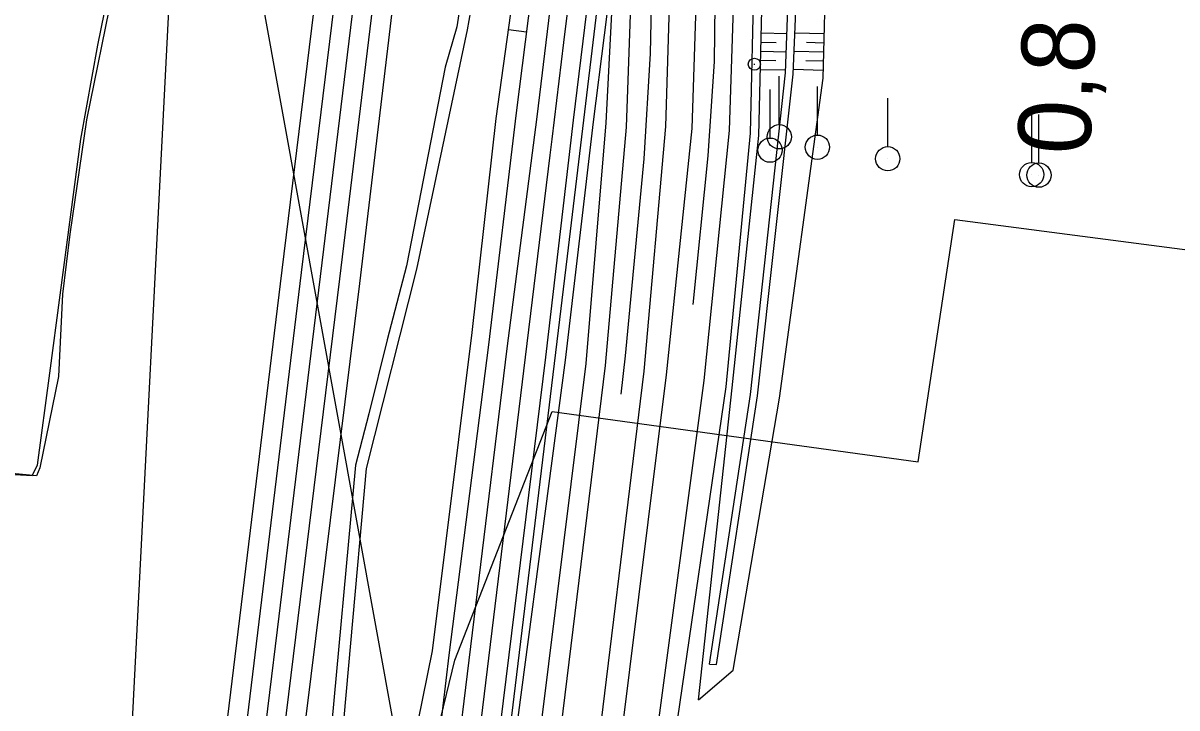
# Model space of a CAD drawing. Extents: x -598638 to -597933, y -1164002 to -1161904.
# Drawn here: x -598553.5 to -598458.3, y -1163554 to -1163497.5 of the extents above; entities that cross this region are included whole.
import ezdxf

# ---------------------------------------------------------------- set-up
doc = ezdxf.new("R2010")
doc.units = 0
for name, color, linetype in [('Vrstva 1', 7, 'Continuous'), ('Vrstva 13', 7, 'Continuous'), ('Vrstva 26', 7, 'Continuous'), ('Vrstva 28', 7, 'Continuous'), ('Vrstva 31', 7, 'Continuous'), ('Vrstva 32', 7, 'Continuous'), ('Vrstva 37', 7, 'Continuous'), ('Vrstva 4', 7, 'Continuous'), ('Vrstva 44', 7, 'Continuous'), ('Vrstva 48', 7, 'Continuous'), ('Vrstva 49', 7, 'Continuous'), ('Vrstva 51', 7, 'Continuous'), ('Vrstva 63', 7, 'Continuous'), ('Vrstva 7', 7, 'Continuous')]:
    doc.layers.add(name, color=color, linetype=linetype)

msp = doc.modelspace()

# ---------------------------------------------------------------- linework, layer by layer
at = {"layer": 'Vrstva 1'}
for points in [[(-598540.061, -1163609.51), (-598538.55, -1163597.18), (-598535.661, -1163573.393), (-598532.502, -1163547.551), (-598529.47, -1163522.734), (-598526.451, -1163497.915), (-598523.419, -1163473.102), (-598521.347, -1163456.074), (-598520.4, -1163448.28), (-598517.374, -1163423.469), (-598514.348, -1163398.653), (-598511.323, -1163373.834), (-598509.75, -1163360.838), (-598508.294, -1163349.021), (-598507.057, -1163338.802)], [(-598533.109, -1163697.673), (-598530.082, -1163672.857), (-598527.054, -1163648.041), (-598524.024, -1163623.225), (-598522.508, -1163610.684), (-598520.997, -1163598.409), (-598517.97, -1163573.59), (-598514.943, -1163548.774), (-598511.916, -1163523.964), (-598510.022, -1163508.437), (-598509.85, -1163507.121), (-598508.889, -1163499.148), (-598506.121, -1163476.682), (-598505.865, -1163474.332), (-598504.943, -1163466.8)], [(-598504.166, -1163528.146), (-598503.792, -1163524.977), (-598502.276, -1163508.73), (-598501.741, -1163500.062), (-598501.244, -1163476.517), (-598501.25, -1163475.071), (-598501.424, -1163467.022)], [(-598498.227, -1163520.757), (-598496.987, -1163508.5), (-598496.459, -1163500.705), (-598496.171, -1163474.917)]]:
    msp.add_lwpolyline(points, dxfattribs=at)
at = {"layer": 'Vrstva 13'}
for points in [[(-598496.865, -1163550.379), (-598493.505, -1163528.163), (-598490.621, -1163501.64), (-598489.924, -1163482.727), (-598490.976, -1163458.949), (-598491.652, -1163439.005), (-598492.756, -1163420.248), (-598491.376, -1163405.706)], [(-598496.865, -1163550.379), (-598496.294, -1163550.405), (-598492.926, -1163528.273), (-598489.969, -1163501.763), (-598489.191, -1163482.813), (-598490.216, -1163459.012), (-598491.02, -1163438.946), (-598492.756, -1163420.248)]]:
    msp.add_lwpolyline(points, dxfattribs=at)
at = {"layer": 'Vrstva 26'}
for points in [[(-598431.799, -1163480.405), (-598431.417, -1163476.751), (-598432.69, -1163475.729), (-598442.616, -1163474.624), (-598460.759, -1163472.82), (-598477.038, -1163471.243), (-598477.967, -1163471.597), (-598478.577, -1163472.787), (-598480.967, -1163481.186), (-598482.275, -1163484.404), (-598483.524, -1163485.456), (-598486.811, -1163485.386), (-598490.508, -1163485.536), (-598512.602, -1163485.892), (-598514.382, -1163486.347), (-598515.51, -1163489.284), (-598515.761, -1163490.906), (-598516.173, -1163494.221), (-598516.873, -1163498.106), (-598521.044, -1163517.837), (-598525.187, -1163534.255), (-598527.784, -1163563.046)], [(-598588.761, -1163677.265), (-598581.48, -1163677.548), (-598580.673, -1163676.998), (-598579.793, -1163670.74), (-598579.104, -1163665.83), (-598575.81, -1163633.898), (-598573.543, -1163615.779), (-598569.61, -1163583.767), (-598565.804, -1163555.196), (-598563.346, -1163534.245), (-598552.733, -1163534.833), (-598552.296, -1163533.988), (-598551.287, -1163526.393), (-598548.728, -1163507.111), (-598547.312, -1163499.378), (-598545.332, -1163489.631)]]:
    msp.add_lwpolyline(points, dxfattribs=at)
at = {"layer": 'Vrstva 28'}
for points in [[(-598454.474, -1163473.952), (-598465.142, -1163473.014), (-598476.47, -1163471.867), (-598477.633, -1163472.175), (-598478.209, -1163473.453), (-598480.422, -1163481.099), (-598481.698, -1163484.769), (-598483.15, -1163485.678), (-598488.83, -1163486.39), (-598490.871, -1163486.311), (-598512.372, -1163485.579), (-598514.383, -1163486.119), (-598515.446, -1163487.289), (-598516.135, -1163489.246), (-598516.85, -1163491.33), (-598516.981, -1163492.995), (-598517.712, -1163497.862), (-598518.68, -1163501.19), (-598521.851, -1163517.567), (-598523.45, -1163523.66), (-598524.97, -1163529.75), (-598526.071, -1163533.98), (-598528.23, -1163557.57)], [(-598545.092, -1163489.642), (-598546.067, -1163494.842), (-598548.252, -1163505.51), (-598549.637, -1163514.935), (-598550.222, -1163519.898), (-598550.57, -1163526.69), (-598552.088, -1163534.212), (-598552.387, -1163534.867), (-598558.986, -1163534.224), (-598563.192, -1163534.27), (-598563.517, -1163536.001), (-598564.063, -1163540.493), (-598564.734, -1163547.322), (-598565.317, -1163553.309), (-598566.354, -1163561.262)]]:
    msp.add_lwpolyline(points, dxfattribs=at)
at = {"layer": 'Vrstva 31'}
for points in [[(-598547.976, -1163487.695), (-598545.092, -1163489.642), (-598546.067, -1163494.842), (-598548.252, -1163505.51), (-598549.637, -1163514.935), (-598550.222, -1163519.898), (-598550.57, -1163526.69), (-598552.088, -1163534.212), (-598552.387, -1163534.867), (-598558.986, -1163534.224), (-598563.192, -1163534.27), (-598563.517, -1163536.001), (-598564.063, -1163540.493), (-598564.734, -1163547.322), (-598565.317, -1163553.309), (-598566.354, -1163561.262)], [(-598516.135, -1163489.246), (-598516.85, -1163491.33), (-598516.981, -1163492.995), (-598517.712, -1163497.862), (-598518.68, -1163501.19), (-598521.851, -1163517.567), (-598523.45, -1163523.66), (-598524.97, -1163529.75), (-598526.071, -1163533.98), (-598528.23, -1163557.57), (-598528.656, -1163562.88), (-598529.14, -1163572.26), (-598530.674, -1163585.905), (-598533.49, -1163606.305), (-598534.2, -1163610.78), (-598536.222, -1163626.077), (-598538.42, -1163640.96), (-598538.84, -1163644.15), (-598539.06, -1163645.8), (-598542.101, -1163668.574), (-598542.12, -1163669.57), (-598542.65, -1163671.24), (-598542.672, -1163673.664)]]:
    msp.add_lwpolyline(points, dxfattribs=at)
at = {"layer": 'Vrstva 32'}
msp.add_lwpolyline([(-598454.474, -1163473.952), (-598465.142, -1163473.014), (-598476.47, -1163471.867), (-598477.633, -1163472.175), (-598478.209, -1163473.453), (-598480.422, -1163481.099), (-598481.698, -1163484.769), (-598483.15, -1163485.678), (-598488.83, -1163486.39), (-598490.871, -1163486.311), (-598512.372, -1163485.579), (-598514.383, -1163486.119), (-598515.446, -1163487.289), (-598516.135, -1163489.246), (-598516.85, -1163491.33), (-598516.981, -1163492.995), (-598517.712, -1163497.862), (-598518.68, -1163501.19), (-598521.851, -1163517.567), (-598523.45, -1163523.66), (-598524.97, -1163529.75), (-598526.071, -1163533.98), (-598528.23, -1163557.57)], dxfattribs=at)
at = {"layer": 'Vrstva 37'}
for p, q in [((-598491.123, -1163505.926), (-598491.123, -1163501.926)), ((-598487.973, -1163506.783), (-598487.973, -1163502.783)), ((-598491.879, -1163507.024), (-598491.879, -1163503.024)), ((-598482.176, -1163507.73), (-598482.176, -1163503.73)), ((-598470.309, -1163509.029), (-598470.309, -1163505.029)), ((-598469.708, -1163509.082), (-598469.708, -1163505.082)), ((-598491.123, -1163506.926), (-598491.123, -1163506.926)), ((-598491.879, -1163508.024), (-598491.879, -1163508.024)), ((-598487.973, -1163507.783), (-598487.973, -1163507.783)), ((-598482.176, -1163508.73), (-598482.176, -1163508.73)), ((-598470.309, -1163510.029), (-598470.309, -1163510.029)), ((-598469.708, -1163510.082), (-598469.708, -1163510.082))]:
    msp.add_line(p, q, dxfattribs=at)
for centre in [(-598491.127, -1163506.921), (-598487.977, -1163507.779), (-598491.882, -1163508.024), (-598482.176, -1163508.732), (-598470.314, -1163510.037), (-598469.712, -1163510.08)]:
    msp.add_circle(centre, 1, dxfattribs=at)
at = {"layer": 'Vrstva 4'}
msp.add_lwpolyline([(-598497.798, -1163553.336), (-598494.995, -1163527.601), (-598492.818, -1163506.812), (-598492.18, -1163480.33), (-598492.913, -1163450.825), (-598495.032, -1163426.834), (-598497.953, -1163400.465), (-598500.02, -1163378.635), (-598500.795, -1163353.032), (-598500.992, -1163338.686), (-598498.929, -1163312.944)], dxfattribs=at)
at = {"layer": 'Vrstva 44'}
for points in [[(-598547.09, -1163680.7), (-598541.17, -1163634.36), (-598541.17, -1163634.36), (-598536.11, -1163593.43), (-598526.29, -1163594.75), (-598522.72, -1163569.98), (-598517.88, -1163550.07), (-598509.86, -1163529.56), (-598479.67, -1163533.72), (-598476.65, -1163513.75), (-598421.89, -1163520.87), (-598414.95, -1163464.46), (-598412.64, -1163442.71)], [(-598503.71, -1163476.022), (-598508.62, -1163516.757), (-598513.545, -1163557.373), (-598518.566, -1163597.711)]]:
    msp.add_lwpolyline(points, dxfattribs=at)
at = {"layer": 'Vrstva 48'}
for p, q in [((-598513.454, -1163498.08), (-598511.957, -1163498.271)), ((-598491.372, -1163499.173), (-598492.633, -1163499.143)), ((-598490.503, -1163498.444), (-598492.615, -1163498.393)), ((-598489.829, -1163498.356), (-598487.416, -1163498.419)), ((-598488.89, -1163499.131), (-598487.436, -1163499.168)), ((-598490.558, -1163499.943), (-598492.651, -1163499.893)), ((-598489.891, -1163499.854), (-598487.455, -1163499.918)), ((-598491.419, -1163500.673), (-598492.669, -1163500.643)), ((-598488.943, -1163500.629), (-598487.475, -1163500.667)), ((-598490.614, -1163501.442), (-598492.687, -1163501.392)), ((-598489.952, -1163501.353), (-598487.494, -1163501.417))]:
    msp.add_line(p, q, dxfattribs=at)
at = {"layer": 'Vrstva 49'}
for points in [[(-598533.45, -1163670.11), (-598536.816, -1163665.931), (-598535.031, -1163653.367), (-598531.766, -1163626.047), (-598527.127, -1163591.782), (-598522.536, -1163563.12), (-598519.726, -1163549.297), (-598516.46, -1163523.044), (-598514.479, -1163505.41), (-598510.834, -1163479.337), (-598507.262, -1163450.223), (-598506.719, -1163427.295), (-598507.24, -1163401.571), (-598507.685, -1163379.523)], [(-598497.798, -1163553.336), (-598494.93, -1163550.871), (-598491.112, -1163528.455), (-598487.512, -1163502.102), (-598487.008, -1163482.722), (-598488.866, -1163459.174), (-598489.773, -1163438.794), (-598491.024, -1163421.023), (-598490.384, -1163406.778), (-598491.376, -1163405.706), (-598492.434, -1163407.048), (-598494.35, -1163419.483)]]:
    msp.add_lwpolyline(points, dxfattribs=at)
at = {"layer": 'Vrstva 51'}
for points in [[(-598501.352, -1163557.294), (-598497.322, -1163527.011), (-598495.22, -1163506.407), (-598494.37, -1163480.26), (-598495.305, -1163450.791), (-598497.315, -1163426.39), (-598500.887, -1163400.701), (-598502.656, -1163378.776), (-598503.412, -1163354.17), (-598503.666, -1163338.931), (-598502.177, -1163312.329), (-598499.265, -1163287.777)], [(-598497.685, -1163287.962), (-598500.382, -1163312.707), (-598501.939, -1163338.79), (-598501.766, -1163354.027), (-598500.944, -1163378.633), (-598499.148, -1163400.517), (-598495.815, -1163426.176), (-598493.871, -1163450.799), (-598492.924, -1163480.338), (-598493.516, -1163506.634), (-598495.537, -1163527.526), (-598499.905, -1163557.48), (-598501.352, -1163557.294)], [(-598538.768, -1163586.309), (-598539.802, -1163586.224), (-598538.809, -1163572.569), (-598537.239, -1163559.929), (-598532.111, -1163517.921), (-598526.717, -1163473.944), (-598521.465, -1163429.602), (-598514.887, -1163376.546), (-598510.204, -1163338.254)], [(-598538.768, -1163586.309), (-598535.642, -1163560.269), (-598530.513, -1163518.107), (-598525.128, -1163474.169), (-598519.579, -1163429.781), (-598513.288, -1163376.745), (-598508.587, -1163338.31)], [(-598534.658, -1163696.543), (-598531.502, -1163671.551), (-598529.287, -1163653.433), (-598525.975, -1163626.57), (-598521.938, -1163592.563), (-598518.465, -1163564.479), (-598513.549, -1163524.372), (-598511.098, -1163505.278), (-598507.979, -1163479.625), (-598504.96, -1163450.403), (-598504.276, -1163427.476), (-598505.025, -1163401.487), (-598505.825, -1163378.899), (-598506.504, -1163355.19), (-598507.471, -1163355.188), (-598510.311, -1163378.58), (-598508.823, -1163379.075)], [(-598576.024, -1163916.782), (-598567.765, -1163849.248), (-598562.666, -1163807.337), (-598557.481, -1163765.121), (-598551.011, -1163711.819), (-598545.358, -1163665.341), (-598539.95, -1163621.544), (-598532.519, -1163560.697), (-598527.374, -1163518.619), (-598522.03, -1163474.673), (-598516.65, -1163430.324), (-598510.109, -1163377.102)], [(-598574.157, -1163917.019), (-598566.089, -1163849.397), (-598561.002, -1163807.966), (-598555.82, -1163765.416), (-598552.514, -1163737.416), (-598552.899, -1163737.337), (-598549.975, -1163711.888), (-598548.115, -1163696.332), (-598547.607, -1163696.337), (-598543.685, -1163665.616), (-598538.398, -1163621.635), (-598530.925, -1163561.125), (-598525.708, -1163519.023), (-598520.47, -1163474.952), (-598514.977, -1163430.656), (-598508.517, -1163377.394)], [(-598534.658, -1163696.543), (-598536.237, -1163696.276), (-598532.874, -1163671.321), (-598530.993, -1163653.169), (-598527.57, -1163626.458), (-598523.511, -1163592.285), (-598520.081, -1163564.257), (-598518.332, -1163549.644), (-598515.065, -1163524.058), (-598512.806, -1163504.945), (-598509.548, -1163479.335), (-598506.49, -1163450.359), (-598505.964, -1163427.237), (-598506.578, -1163401.572), (-598507.29, -1163379.316), (-598507.685, -1163379.523), (-598508.823, -1163379.075)], [(-598506.681, -1163562.454), (-598502.255, -1163526.242), (-598500.466, -1163506.079), (-598499.676, -1163479.844), (-598500.384, -1163450.749), (-598501.179, -1163427.388), (-598500.18, -1163427.338), (-598498.539, -1163450.705), (-598497.484, -1163480.021), (-598498.326, -1163506.229), (-598500.451, -1163526.549), (-598504.238, -1163557.006), (-598504.733, -1163556.998), (-598505.412, -1163562.492), (-598506.681, -1163562.454)], [(-598524.957, -1163654.342), (-598526.23, -1163654.147), (-598522.865, -1163627.13), (-598518.778, -1163593.06), (-598515.262, -1163564.784), (-598510.38, -1163525.074), (-598508.089, -1163505.541), (-598503.827, -1163470.713), (-598502.877, -1163470.75), (-598502.82, -1163479.855), (-598503.743, -1163506.131), (-598505.469, -1163525.76), (-598510.31, -1163565.263), (-598511.959, -1163565.174), (-598507.047, -1163525.607), (-598505.405, -1163505.762), (-598504.664, -1163491.368), (-598506.458, -1163505.698), (-598508.776, -1163525.335), (-598514.016, -1163564.95), (-598517.513, -1163593.481), (-598521.525, -1163627.349), (-598524.957, -1163654.342)]]:
    msp.add_lwpolyline(points, dxfattribs=at)
at = {"layer": 'Vrstva 63'}
for p in [(-598554.868, -1163759.055), (-598520.489, -1163568.592)]:
    msp.add_line(p, (-598539.744, -1163462.649), dxfattribs=at)
at = {"layer": 'Vrstva 7'}
msp.add_line((-598493.226, -1163500.943), (-598493.126, -1163500.943), dxfattribs=at)
msp.add_circle((-598493.176, -1163500.943), 0.5, dxfattribs=at)

# ---------------------------------------------------------------- texts
msp.add_text('0,8', height=6, rotation=87.64902, dxfattribs=at).set_placement((-598465.505, -1163508.46))

doc.saveas('drawing.dxf')
